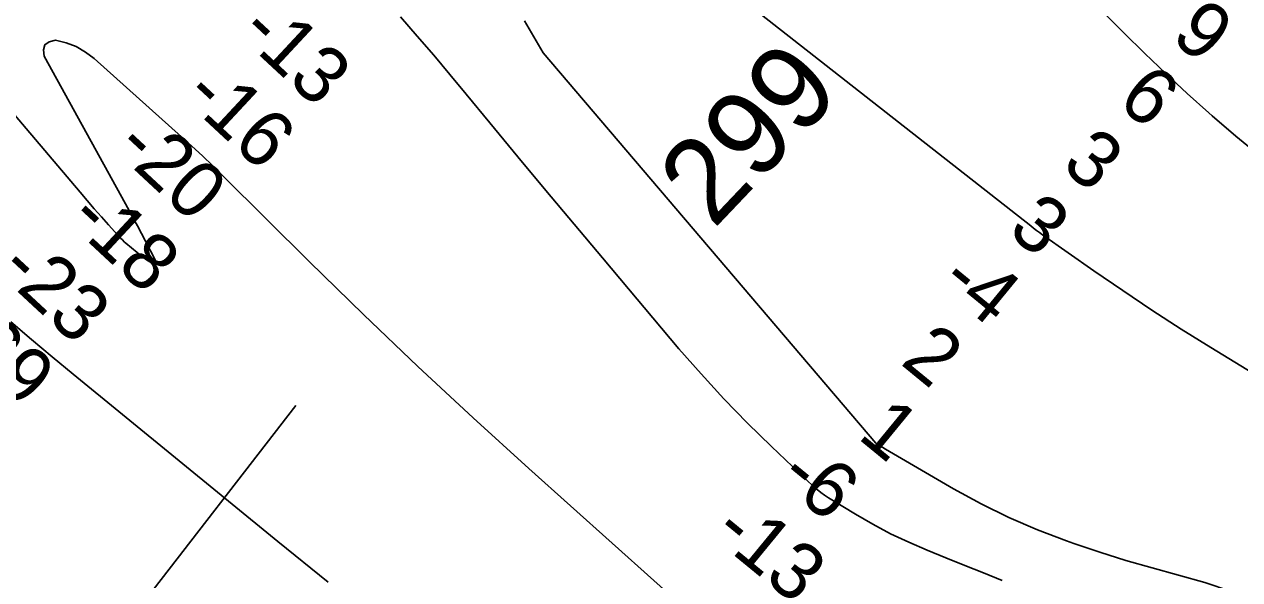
# Model space of a CAD drawing. Extents: x 3161615 to 3199515, y 867541 to 892976.
# Drawn here: x 3183730 to 3185169, y 881796 to 882454 of the extents above; entities that cross this region are included whole.
import ezdxf

# ---------------------------------------------------------------- set-up
doc = ezdxf.new("R2010")
doc.units = 0
for name, color, linetype in [('V-RIVR-IDEN', 7, 'Continuous'), ('V-RIVR-RANG', 7, 'Continuous'), ('V-TOPO-DPTH', 7, 'Continuous'), ('V-TOPO-MINR', 7, 'Continuous')]:
    doc.layers.add(name, color=color, linetype=linetype)

msp = doc.modelspace()

# ---------------------------------------------------------------- linework, layer by layer
at = {"layer": 'V-RIVR-RANG'}
msp.add_line((3181801.2, 879095.8), (3184051.7, 882002.4), dxfattribs=at)
at = {"layer": 'V-TOPO-DPTH'}
for points in [[(3183452.3, 882661), (3183796.2, 882255), (3183804.5, 882245.2), (3183813, 882235.5), (3183821.5, 882225.9), (3183830, 882216.3), (3183844.4, 882200.4), (3183845.9, 882198.9), (3183849, 882195.9), (3183850.6, 882194.5), (3183870.5, 882178.1), (3183873.2, 882176), (3183876, 882174.2), (3183878.9, 882172.7), (3183882, 882171.4), (3183883.7, 882171.5), (3183884.9, 882172.1), (3183885.3, 882173.4), (3183885.2, 882175), (3183873.7, 882197.2), (3183868.9, 882206.3), (3183864.1, 882215.4), (3183859.2, 882224.4), (3183854.3, 882233.4), (3183753.8, 882416.2), (3183753, 882423.8), (3183754.5, 882429.8), (3183759.7, 882433.3), (3183767.1, 882435.1), (3183779.7, 882432), (3183791.6, 882427.5), (3183802.5, 882421.1), (3183812.9, 882413.3), (3183916.2, 882320.8), (3183928.7, 882309.4), (3183941, 882298), (3183953.2, 882286.3), (3183965.2, 882274.5), (3184067.9, 882172.6), (3184131.7, 882110.3), (3184196.1, 882048.6), (3184261.4, 881987.9), (3184327.3, 881927.9), (3184524.7, 881751)], [(3183452.3, 882661), (3183796.2, 882255), (3183804.5, 882245.2), (3183813, 882235.5), (3183821.5, 882225.9), (3183830, 882216.3), (3183844.4, 882200.4), (3183845.9, 882198.9), (3183849, 882195.9), (3183850.6, 882194.5), (3183870.5, 882178.1), (3183873.2, 882176), (3183876, 882174.2), (3183878.9, 882172.7), (3183882, 882171.4), (3183883.7, 882171.5), (3183884.9, 882172.1), (3183885.3, 882173.4), (3183885.2, 882175), (3183873.7, 882197.2), (3183868.9, 882206.3), (3183864.1, 882215.4), (3183859.2, 882224.4), (3183854.3, 882233.4), (3183753.8, 882416.2), (3183753, 882423.8), (3183754.5, 882429.8), (3183759.7, 882433.3), (3183767.1, 882435.1), (3183779.7, 882432), (3183791.6, 882427.5), (3183802.5, 882421.1), (3183812.9, 882413.3), (3183916.2, 882320.8), (3183928.7, 882309.4), (3183941, 882298), (3183953.2, 882286.3), (3183965.2, 882274.5), (3184067.9, 882172.6), (3184131.7, 882110.3), (3184196.1, 882048.6), (3184261.4, 881987.9), (3184327.3, 881927.9), (3184524.7, 881751)], [(3185453.7, 881875.9), (3185134.8, 882071.1), (3185099.7, 882093), (3185064.8, 882115.4), (3185030.4, 882138.5), (3184996.3, 882162), (3184935.6, 882204.6), (3184932, 882207.2), (3184928.5, 882209.7), (3184925, 882212.4), (3184921.5, 882215.1), (3184508, 882539.6)], [(3185453.7, 881875.9), (3185134.8, 882071.1), (3185099.7, 882093), (3185064.8, 882115.4), (3185030.4, 882138.5), (3184996.3, 882162), (3184935.6, 882204.6), (3184932, 882207.2), (3184928.5, 882209.7), (3184925, 882212.4), (3184921.5, 882215.1), (3184508, 882539.6)], [(3184175.7, 882462.6), (3184195.3, 882440), (3184214.8, 882417.2), (3184234.1, 882394.3), (3184253.2, 882371.3), (3184281.3, 882337.2), (3184314.5, 882297.1), (3184347.7, 882257), (3184381.1, 882217.1), (3184414.6, 882177.3), (3184505.1, 882069.7), (3184531.3, 882039.7), (3184558.2, 882010.2), (3184586.1, 881981.6), (3184614.6, 881953.7), (3184664.6, 881906.6), (3184668.7, 881902.9), (3184673.1, 881899.3), (3184677.6, 881896.1), (3184682.3, 881893), (3184714.1, 881873.6), (3184734.7, 881861.7), (3184755.7, 881850.5), (3184777.2, 881840.4), (3184799.1, 881830.9), (3184821.2, 881822), (3184843.4, 881813), (3184865.5, 881804.1), (3184887.6, 881795.2)], [(3184887.6, 881795.2), (3184865.5, 881804.1), (3184843.4, 881813), (3184821.2, 881822), (3184799.1, 881830.9), (3184777.2, 881840.4), (3184755.7, 881850.5), (3184734.7, 881861.7), (3184714.1, 881873.6), (3184682.3, 881893), (3184677.6, 881896.1), (3184673.1, 881899.3), (3184668.7, 881902.9), (3184664.6, 881906.6), (3184614.6, 881953.7), (3184586.1, 881981.6), (3184558.2, 882010.2), (3184531.3, 882039.7), (3184505.1, 882069.7), (3184414.6, 882177.3), (3184381.1, 882217.1), (3184347.7, 882257), (3184314.5, 882297.1), (3184281.3, 882337.2), (3184253.2, 882371.3), (3184234.1, 882394.3), (3184214.8, 882417.2), (3184195.3, 882440), (3184175.7, 882462.6)], [(3184090.1, 881793.2), (3184030.3, 881841.2), (3183788, 882039.5), (3183763.3, 882059.9), (3183738.6, 882080.5), (3183714.2, 882101.4)], [(3184090.1, 881793.2), (3184030.3, 881841.2), (3183788, 882039.5), (3183763.3, 882059.9), (3183738.6, 882080.5), (3183714.2, 882101.4)]]:
    msp.add_lwpolyline(points, dxfattribs=at)
at = {"layer": 'V-TOPO-MINR'}
for points in [[(3186135.7, 881728.3), (3186124.3, 881732.5), (3186032.9, 881765.8), (3185976.5, 881788.1), (3185921, 881812.4), (3185866.9, 881839.7), (3185813.8, 881868.9), (3185661.8, 881957.9), (3185635.3, 881974), (3185609.1, 881990.7), (3185583.5, 882008.2), (3185558.2, 882026.2), (3185251.4, 882252.7), (3185221.9, 882275.1), (3185192.8, 882298), (3185164.3, 882321.6), (3185136.2, 882345.7), (3185132.5, 882349), (3185106.8, 882372.1), (3185081.5, 882395.5), (3185056.5, 882419.4), (3185031.9, 882443.7), (3184632.3, 882844.3)], [(3183452.3, 882661), (3183796.2, 882255), (3183804.5, 882245.2), (3183813, 882235.5), (3183821.5, 882225.9), (3183830, 882216.3), (3183844.4, 882200.4), (3183845.9, 882198.9), (3183849, 882195.9), (3183850.6, 882194.5), (3183870.5, 882178.1), (3183873.2, 882176), (3183876, 882174.2), (3183878.9, 882172.7), (3183882, 882171.4), (3183883.7, 882171.5), (3183884.9, 882172.1), (3183885.3, 882173.4), (3183885.2, 882175), (3183873.7, 882197.2), (3183868.9, 882206.3), (3183864.1, 882215.4), (3183859.2, 882224.4), (3183854.3, 882233.4), (3183753.8, 882416.2), (3183753, 882423.8), (3183754.5, 882429.8), (3183759.7, 882433.3), (3183767.1, 882435.1), (3183779.7, 882432), (3183791.6, 882427.5), (3183802.5, 882421.1), (3183812.9, 882413.3), (3183916.2, 882320.8), (3183928.7, 882309.4), (3183941, 882298), (3183953.2, 882286.3), (3183965.2, 882274.5), (3184067.9, 882172.6), (3184131.7, 882110.3), (3184196.1, 882048.6), (3184261.4, 881987.9), (3184327.3, 881927.9), (3184524.7, 881751)], [(3185453.7, 881875.9), (3185134.8, 882071.1), (3185099.7, 882093), (3185064.8, 882115.4), (3185030.4, 882138.5), (3184996.3, 882162), (3184935.6, 882204.6), (3184932, 882207.2), (3184928.5, 882209.7), (3184925, 882212.4), (3184921.5, 882215.1), (3184508, 882539.6)], [(3184887.6, 881795.2), (3184865.5, 881804.1), (3184843.4, 881813), (3184821.2, 881822), (3184799.1, 881830.9), (3184777.2, 881840.4), (3184755.7, 881850.5), (3184734.7, 881861.7), (3184714.1, 881873.6), (3184682.3, 881893), (3184677.6, 881896.1), (3184673.1, 881899.3), (3184668.7, 881902.9), (3184664.6, 881906.6), (3184614.6, 881953.7), (3184586.1, 881981.6), (3184558.2, 882010.2), (3184531.3, 882039.7), (3184505.1, 882069.7), (3184414.6, 882177.3), (3184381.1, 882217.1), (3184347.7, 882257), (3184314.5, 882297.1), (3184281.3, 882337.2), (3184253.2, 882371.3), (3184234.1, 882394.3), (3184214.8, 882417.2), (3184195.3, 882440), (3184175.7, 882462.6)], [(3185188, 881770.7), (3185158.1, 881782.6), (3185127.5, 881792.7), (3185096.4, 881801.5), (3185065.2, 881809.9), (3185034.1, 881818.8), (3185003.3, 881828.6), (3184972.7, 881838.9), (3184964, 881841.9), (3184929.5, 881855.2), (3184895.7, 881869.6), (3184862.7, 881886), (3184830.3, 881903.7), (3184749.5, 881950.7), (3184738.3, 881957.8), (3184344.4, 882420.1), (3184333.4, 882439.1), (3184322.2, 882458)], [(3184090.1, 881793.2), (3184030.3, 881841.2), (3183788, 882039.5), (3183763.3, 882059.9), (3183738.6, 882080.5), (3183714.2, 882101.4)]]:
    msp.add_lwpolyline(points, dxfattribs=at)

# ---------------------------------------------------------------- texts
at = {"layer": 'V-RIVR-IDEN'}
msp.add_text('299', height=100, rotation=46.4945, dxfattribs=at).set_placement((3184546.1, 882210.4))
at = {"layer": 'V-RIVR-RANG'}
for s, rotation, p in [('9', 320.6322, (3185085.8, 882436.6)), ('-13', 317.0767, (3183982.1, 882441.6)), ('6', 320.6322, (3185022.1, 882359.5)), ('-16', 317.0767, (3183916.3, 882366.3)), ('-20', 317.0767, (3183835.2, 882305.1)), ('3', 320.6322, (3184956.1, 882284.3)), ('3', 320.6322, (3184892.6, 882207.1)), ('-18', 317.0767, (3183779.7, 882220.2)), ('-23', 317.0767, (3183697.3, 882160.3)), ('-4', 320.6322, (3184811.3, 882144.4)), ('-29', 317.0767, (3183631.6, 882084.8)), ('2', 320.6322, (3184765.9, 882052.3)), ('1', 320.6322, (3184715.2, 881964.5)), ('-6', 320.6322, (3184620.5, 881912.9)), ('-13', 320.6322, (3184542.7, 881847.4))]:
    msp.add_text(s, height=67, rotation=rotation, dxfattribs=at).set_placement(p)

doc.saveas('drawing.dxf')
